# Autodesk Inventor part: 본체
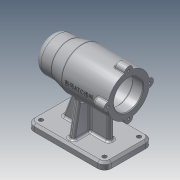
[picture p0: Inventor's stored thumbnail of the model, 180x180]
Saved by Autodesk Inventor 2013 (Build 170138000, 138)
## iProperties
Created: 2019-07
Part Number: 본체
Material: 알루미늄 6061
Document SubType Name: Modeling
Designer: user
Density: 2.71 g/cm^3
Mass: 646.775 g
Surface Area: 654.094 cm^2
Volume: 238.662 cm^3
Author: user
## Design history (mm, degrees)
sketch "스케치1"
  geometry: L1 (0, 0)-(0, 112); L2 (0, 112)-(25, 112); L3 (25, 112)-(25, 87); L4 (25, 87)-(30, 67); L5 (30, 67)-(30, 0); L6 (30, 0)-(0, 0); 1 further point
  constraints: 12 end point, 2 parallel, 2 perpendicular, 1 coincident, 1 vertical
  dimensions: "d0" = 112 distance of L1.start L1.end; "d1" = 50 diameter of L3 L1; "d2" = 60 diameter of L5 L1; "d3" = 25 distance from line of L2 L3.end; "d4" = 45 distance from line of L2 L4.end
revolve "회전1" sketch "스케치1" stored, may be unused: angle "d5" = 90 deg
fillet "모깎기1" dims "d6" = 10
sketch "스케치2"
  geometry: L1 (-15, 112)-(15, 112) reference; L2 (0, 0)-(0, 112); L3 (0, 0)-(21, 0); L4 (21, 0)-(21, 15); L5 (21, 15)-(24, 15); L6 (24, 15)-(24, 69); L7 (24, 69)-(21, 69); L8 (21, 69)-(21, 81); L9 (21, 81)-(17.5, 81); L10 (17.5, 81)-(17.5, 99); L11 (17.5, 99)-(16, 99); L12 (16, 99)-(16, 103); L13 (16, 103)-(10.5, 103); L14 (10.5, 103)-(10.5, 106); L15 (10.5, 106)-(0, 106)
  constraints: 28 end point, 9 parallel, 3 perpendicular, 1 collinear, 1 midpoint, 1 point on line
  dimensions: "d7" = 42 diameter of L4 L2; "d9" = 48 diameter of L6 L2; "d10" = 42 diameter of L8 L2; "d11" = 35 diameter of L10 L2; "d12" = 32 diameter of L12 L2; "d13" = 21 diameter of L14 L2; "d14" = 15 distance from line of L2.start L5; "d15" = 54 distance of L5.end L6.end; "d16" = 12 distance of L7.end L8.end; "d17" = 18 distance of L9.end L10.end; "d18" = 4 distance of L11.end L12.end; "d19" = 3 distance of L13.end L14.end
revolve "회전2" sketch "스케치2" stored, may be unused: angle "d20" = 90 deg
fillet "모깎기9" dims "d79" = 3
node "작업 평면1"
sketch "스케치3"
  geometry: L1 (-30, 0)-(30, 0) reference; L2 (35, 0)-(-35, 0); L3 (-35, 0)-(-35, 112); L4 (-35, 112)-(35, 112); L5 (35, 112)-(35, 0); 2 further points
  constraints: 8 end point, 2 midpoint, 2 parallel, 1 horizontal, 1 perpendicular
  dimensions: "d22" = 70 distance of L3.end L4.end; "d23" = 112 distance of L2.end L3.end
extrude "돌출1" join sketch "스케치3" distance "d24" = 10; taper "d25" = 0 deg
node "작업 평면2"
sketch "스케치4"
  geometry: L1 (35, -70)-(35, -80) reference; L2 (35, -80)-(-35, -80) reference; L3 (-35, -80)-(-35, -70) reference; L4 (-35, -70)-(35, -70) reference; L5 (-28, -70)-(-19.654, -22.666); L6 (19.654, -22.666)-(28, -70); C1 r 24 at (0, 0) reference; A1 r 30 centre (0, 0) between (-19.654, -22.666) and (19.654, -22.666) reference; 1 further point
  constraints: 4 end point, 2 point on circle, 2 point on line
  dimensions: "d27" = 7 distance from line of L3 L5.start; "d28" = 7 distance from line of L1 L6.end; "d29" = 100 deg angle of L4 L6; "d30" = 100 deg angle of L4 L5
extrude "돌출2" join sketch "스케치4" stored distance "d31" = 8; taper "d32" = 0 deg
sketch "스케치5"
  geometry: L1 (25, 102)-(25, 87) reference; L2 (25, 87)-(29.91, 67.358) reference; L3 (30, 66.631)-(30, 0) reference; L4 (30, 0)-(21, 0) reference; L5 (21, 0)-(21, 15) reference; L6 (21, 15)-(24, 15) reference; L7 (24, 15)-(24, 69) reference; L8 (24, 69)-(21, 69) reference; L9 (21, 69)-(21, 81) reference; L10 (21, 81)-(17.5, 81) reference; L11 (17.5, 81)-(17.5, 99) reference; L12 (17.5, 99)-(16, 99) reference; L13 (16, 99)-(16, 103) reference; L14 (16, 103)-(10.5, 103) reference; L15 (10.5, 103)-(10.5, 106) reference; L16 (10.5, 106)-(-10.5, 106) reference; L17 (-10.5, 106)-(-10.5, 103) reference; L18 (-10.5, 103)-(-16, 103) reference; L19 (-16, 103)-(-16, 99) reference; L20 (-16, 99)-(-17.5, 99) reference; L21 (-17.5, 99)-(-17.5, 81) reference; L22 (-17.5, 81)-(-21, 81) reference; L23 (-21, 81)-(-21, 69) reference; L24 (-21, 69)-(-24, 69) reference; L25 (-24, 69)-(-24, 15) reference; L26 (-24, 15)-(-21, 15) reference; L27 (-21, 15)-(-21, 0) reference; L28 (-21, 0)-(-30, 0) reference; L29 (-30, 0)-(-30, 52) reference; L30 (-30, 52)-(-70, 52) reference; L31 (-70, 52)-(-70, 0) reference; L32 (-70, 0)-(-80, 0) reference; L33 (-80, 0)-(-80, 112) reference; L34 (-80, 112)-(-70, 112) reference; L35 (-70, 112)-(-70, 60) reference; L36 (-70, 60)-(-30, 60) reference; L37 (-30, 60)-(-30, 66.631) reference; L38 (-29.91, 67.358)-(-25, 87) reference; L39 (-25, 87)-(-25, 102) reference; L40 (-15, 112)-(15, 112) reference; L41 (-27.607, 76.57)-(-70, 92); A1 r 10 centre (15, 102) between (25, 102) and (15, 112) reference; A2 r 10 centre (-15, 102) between (-15, 112) and (-25, 102) reference; A3 r 3 centre (27, 66.631) between (30, 66.631) and (29.91, 67.358) reference; A4 r 3 centre (-27, 66.631) between (-29.91, 67.358) and (-30, 66.631) reference; 1 further point
  constraints: 2 end point, 2 point on line
  dimensions: "d33" = 20 distance from line of L34 L41.end; "d34" = 110 deg angle of L35 L41
feature "리브1" sketch "스케치5" dims "d35" = 1, "d36" = 8, "d37" = 0, "d38" = 0, "d39" = 1, "d40" = 1
sketch "스케치6"
  geometry: L1 (25, 102)-(25, 87) reference; L2 (25, 87)-(29.91, 67.358) reference; L3 (30, 66.631)-(30, 0) reference; L4 (30, 0)-(21, 0) reference; L5 (21, 0)-(21, 15) reference; L6 (21, 15)-(24, 15) reference; L7 (24, 15)-(24, 69) reference; L8 (24, 69)-(21, 69) reference; L9 (21, 69)-(21, 81) reference; L10 (21, 81)-(17.5, 81) reference; L11 (17.5, 81)-(17.5, 99) reference; L12 (17.5, 99)-(16, 99) reference; L13 (16, 99)-(16, 103) reference; L14 (16, 103)-(10.5, 103) reference; L15 (10.5, 103)-(10.5, 106) reference; L16 (10.5, 106)-(-10.5, 106) reference; L17 (-10.5, 106)-(-10.5, 103) reference; L18 (-10.5, 103)-(-16, 103) reference; L19 (-16, 103)-(-16, 99) reference; L20 (-16, 99)-(-17.5, 99) reference; L21 (-17.5, 99)-(-17.5, 81) reference; L22 (-17.5, 81)-(-21, 81) reference; L23 (-21, 81)-(-21, 69) reference; L24 (-21, 69)-(-24, 69) reference; L25 (-24, 69)-(-24, 15) reference; L26 (-24, 15)-(-21, 15) reference; L27 (-21, 15)-(-21, 0) reference; L28 (-21, 0)-(-30, 0) reference; L29 (-30, 0)-(-30, 52) reference; L30 (-30, 52)-(-70, 52) reference; L31 (-70, 52)-(-70, 0) reference; L32 (-70, 0)-(-80, 0) reference; L33 (-80, 0)-(-80, 112) reference; L34 (-80, 112)-(-70, 112) reference; L35 (-70, 112)-(-70, 92) reference; L36 (-70, 92)-(-27.607, 76.57) reference; L37 (-27.607, 76.57)-(-25, 87) reference; L38 (-25, 87)-(-25, 102) reference; L39 (-15, 112)-(15, 112) reference; L40 (-30, 25)-(-70, 25); A1 r 10 centre (15, 102) between (25, 102) and (15, 112) reference; A2 r 10 centre (-15, 102) between (-15, 112) and (-25, 102) reference; A3 r 3 centre (27, 66.631) between (30, 66.631) and (29.91, 67.358) reference; 1 further point
  constraints: 2 end point, 2 point on line, 1 perpendicular
  dimensions: "d41" = 25 distance between parallel lines of L32 L40
feature "리브2" sketch "스케치6" dims "d42" = 1, "d43" = 8, "d44" = 0, "d45" = 0, "d46" = 1, "d47" = 1
sketch "스케치7"
  geometry: L1 (0, 0)-(0, 30); C1 r 30 at (0, 0) reference; C2 r 6 at (0, 30)
  constraints: 2 end point, 1 centre point, 1 coincident, 1 vertical
  dimensions: "d48" = 30 distance of L1.start L1.end; "d49" = 12 diameter of C2
extrude "돌출3" join sketch "스케치7" distance "d50" = 16; taper "d51" = 0 deg
sketch "스케치8"
  geometry: A1 r 6 centre (0, 0) between (5.97, -0.6) and (-5.97, -0.6) reference; 1 further point
  constraints: 1 coincident
hole "구멍1" sketch "스케치8" at (0, 0) diameter "d52" = 3.242; stored, may be unused: countersink angle "d56" = 90 deg, drill point angle "d58" = 118 deg; dims "d53" = 8, "d54" = 4, "d55" = 2, "d57" = 11
fillet "모깎기2" dims "d62" = 10
sketch "스케치9"
  geometry: A1 r 10 centre (-25, -102) between (-35, -102) and (-25, -112) reference; A2 r 10 centre (25, -102) between (25, -112) and (35, -102) reference; A3 r 10 centre (25, -10) between (35, -10) and (25, 0) reference; A4 r 10 centre (-25, -10) between (-25, 0) and (-35, -10) reference; 5 further points
  constraints: 4 coincident
hole "구멍2" sketch "스케치9" at (-25, -10), (-25, -102), (25, -102), (25, -10) diameter "d63" = 6; stored, may be unused: countersink angle "d67" = 90 deg, drill point angle "d69" = 118 deg; dims "d64" = 8, "d65" = 4, "d66" = 2, "d68" = 11
fillet "모깎기3" dims "d70" = 3
fillet "모깎기4" dims "d71" = 0.3
fillet "모깎기5" dims "d72" = 3
chamfer "모따기1" distance "d73" = 1; stored, may be unused: second distance "d74" = 2, angle "d75" = 45 deg
fillet "모깎기6" dims "d76" = 3
fillet "모깎기7" dims "d77" = 1
fillet "모깎기8" dims "d78" = 3
chamfer "모따기2" distance "d80" = 3; stored, may be unused: second distance "d81" = 2, angle "d82" = 45 deg
fillet "모깎기10" dims "d83" = 3
fillet "모깎기11" dims "d84" = 3
node "작업 평면3"
sketch "스케치10"
  geometry: 2 further points
  constraints: 1 vertical alignment, 1 other
  dimensions: "d86" = 42 distance of point (0, 0) point (0, 42)
feature "엠보싱1" sketch "스케치10" dims "d87" = 0.5, "d88" = 0
node "솔리드1"
pattern_circular "원형 패턴1" dims angle "d60" = 360 deg
node "절단 모서리 투영1"
node "절단 모서리 투영2"
node "절단 모서리 투영3"
other parameters: "d26" = 56
